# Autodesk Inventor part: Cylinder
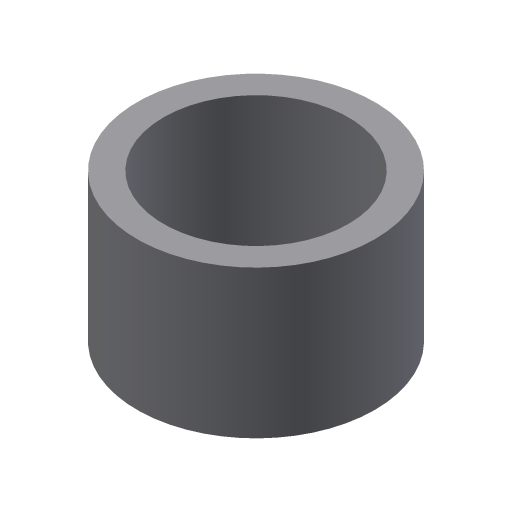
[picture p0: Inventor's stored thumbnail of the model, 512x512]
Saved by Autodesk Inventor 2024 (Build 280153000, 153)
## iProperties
Shininess: 64.0
Length Units: 11269
Angle Units: 11279
Time Units: 11290
Mass Units: 11283
Length Display Precision: 3
Angle Display Precision: 2
Compacted: True
Part Number: Cylinder
Document SubType Name: Modeling
Created: 2003-01
Designer: Owner
Density: 1 g/cm^3
Material: Generic
Appearance: Default
Density: 0.0
Volumn: 0.0
Area: 0.0
PropertySet Name: Model Information
Control State: 0
Master: False
Checked Out: False
Author: Owner
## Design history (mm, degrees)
sketch "Sketch1"
  geometry: C1 r 112.5 at (0, 0); C2 r 87.5 at (0, 0)
  constraints: 2 centre point, 1 coincident, 1 concentric
  dimensions: "d0" = 225 diameter of C1; "d1" = 175 diameter of C2
extrude "Extrusion1" new body sketch "Sketch1" stored distance "d2" = 140; taper "d3" = 0 deg
body "Solid1"
